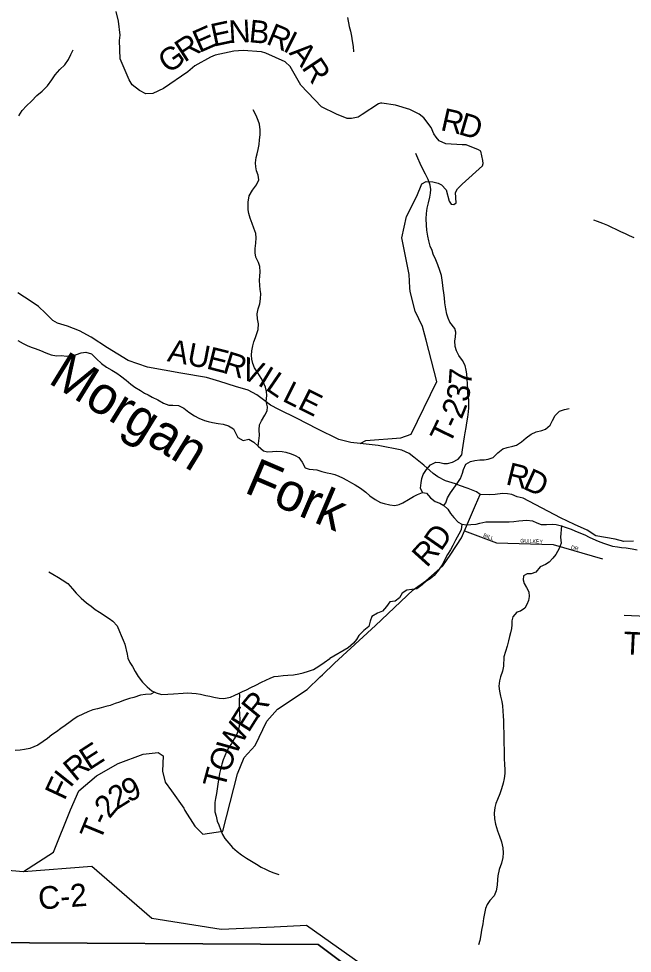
# Model space of a CAD drawing. Extents: x 1578669 to 1989827, y 208020 to 553079.
# Drawn here: x 1759764 to 1767882, y 406595 to 418953 of the extents above; entities that cross this region are included whole.
import ezdxf

# ---------------------------------------------------------------- set-up
doc = ezdxf.new("R2010")
doc.units = 0
for name, color, linetype in [('GM_X_County_Road', 7, 'Continuous'), ('GM_X_County_Road_Text', 7, 'Continuous'), ('GM_X_Minor_River', 7, 'Continuous'), ('GM_X_Minor_River_Text', 7, 'Continuous'), ('GM_X_Township', 7, 'Continuous'), ('GM_X_Township_Road', 7, 'Continuous'), ('GM_X_Township_Road_Text', 7, 'Continuous'), ('GM_X_Township_Subdivision', 7, 'Continuous'), ('GM_X_Township_Subdivision_Text', 7, 'Continuous')]:
    doc.layers.add(name, color=color, linetype=linetype)

msp = doc.modelspace()

# ---------------------------------------------------------------- linework, layer by layer
at = {"layer": 'GM_X_County_Road'}
for points in [[(1767900, 412043), (1767770, 412040), (1767655, 412072), (1767398, 412113), (1767286, 412188), (1767117, 412263), (1766932, 412354), (1766439, 412614), (1766357, 412631), (1766289, 412661), (1766229, 412670), (1766166, 412674), (1766069, 412663), (1765993, 412659), (1765870, 412663), (1765820, 412695), (1765709, 412742), (1765596, 412780), (1765541, 412802), (1765409, 412841), (1765308, 412893), (1765248, 412940), (1765124, 413048), (1764991, 413157), (1764930, 413203), (1764833, 413246), (1764520, 413310), (1764284, 413336), (1764160, 413350), (1764001, 413388), (1763713, 413529), (1763449, 413666), (1763205, 413787), (1763095, 413841), (1763020, 413898), (1762913, 413981), (1762798, 414043), (1762633, 414091), (1762424, 414157), (1762249, 414207), (1761908, 414267), (1761467, 414344), (1761213, 414435), (1760939, 414601), (1760725, 414741), (1760568, 414825), (1760411, 414885), (1760276, 414927), (1760218, 414960), (1760119, 415059), (1760027, 415148), (1759929, 415215), (1759751, 415328)], [(1758349, 408284), (1758363, 408267), (1758628, 407870), (1758709, 407803), (1758726, 407779), (1758795, 407679), (1758805, 407674), (1758871, 407657), (1758962, 407655), (1759126, 407681), (1759270, 407715), (1759375, 407728), (1759549, 407716), (1759674, 407691), (1759826, 407677), (1760733, 407747), (1761526, 407058), (1762445, 406912), (1763145, 406947), (1763146, 406947)], [(1763146, 406947), (1763573, 406968), (1765203, 405810), (1765879, 405766), (1766567, 405904), (1768602, 405235)]]:
    msp.add_lwpolyline(points, dxfattribs=at)
at = {"layer": 'GM_X_Minor_River'}
for points in [[(1764114, 418969), (1764138, 418848), (1764152, 418786), (1764166, 418720), (1764176, 418658), (1764188, 418585), (1764194, 418515)], [(1759764, 417667), (1759812, 417739), (1759868, 417801), (1759932, 417863), (1760006, 417935), (1760075, 417996), (1760145, 418066), (1760203, 418144), (1760247, 418212), (1760309, 418281), (1760373, 418343), (1760425, 418413), (1760453, 418477), (1760483, 418540)], [(1762932, 413302), (1762948, 413442), (1762946, 413515), (1762948, 413581), (1762976, 413635), (1763020, 413709), (1763052, 413768), (1763056, 413820), (1763038, 413892), (1763046, 413972), (1763044, 414024), (1763028, 414081), (1763000, 414151), (1762972, 414201), (1762928, 414271), (1762884, 414338), (1762862, 414392), (1762848, 414452), (1762844, 414504), (1762850, 414563), (1762862, 414625), (1762874, 414679), (1762898, 414737), (1762916, 414789), (1762933, 414844), (1762937, 414920), (1762923, 414986), (1762919, 415052), (1762931, 415115), (1762955, 415183), (1762965, 415249), (1762967, 415319), (1762959, 415372), (1762953, 415424), (1762949, 415494), (1762953, 415550), (1762957, 415604), (1762955, 415677), (1762935, 415731), (1762901, 415801), (1762891, 415855), (1762893, 415914), (1762901, 415984), (1762905, 416054), (1762901, 416112), (1762877, 416185), (1762853, 416243), (1762827, 416313), (1762807, 416375), (1762801, 416425), (1762799, 416476), (1762799, 416528), (1762815, 416612), (1762859, 416686), (1762910, 416757), (1762940, 416821), (1762934, 416885), (1762912, 416941), (1762902, 416996), (1762898, 417046), (1762906, 417116), (1762918, 417166), (1762932, 417224), (1762944, 417287), (1762952, 417349), (1762958, 417417), (1762960, 417483), (1762948, 417558), (1762932, 417608), (1762904, 417674), (1762866, 417746)], [(1765108, 412687), (1765080, 412743), (1765090, 412814), (1765098, 412872), (1765116, 412926), (1765158, 412992), (1765213, 413053), (1765285, 413091), (1765337, 413085), (1765387, 413073), (1765437, 413071), (1765505, 413091), (1765579, 413127), (1765627, 413185), (1765637, 413253), (1765643, 413309), (1765653, 413368), (1765661, 413422), (1765671, 413478), (1765683, 413548), (1765691, 413611), (1765704, 413683), (1765714, 413753), (1765718, 413807), (1765720, 413859), (1765718, 413916), (1765708, 413992), (1765704, 414054), (1765702, 414122), (1765698, 414191), (1765692, 414255), (1765684, 414305), (1765670, 414369), (1765634, 414434), (1765588, 414500), (1765558, 414560), (1765540, 414620), (1765536, 414693), (1765544, 414743), (1765548, 414807), (1765534, 414857), (1765470, 414938), (1765446, 414992), (1765428, 415046), (1765414, 415116), (1765404, 415194), (1765396, 415263), (1765390, 415327), (1765382, 415383), (1765372, 415464), (1765356, 415558), (1765336, 415624), (1765310, 415700), (1765284, 415763), (1765248, 415839), (1765234, 415889), (1765210, 415947), (1765190, 416016), (1765178, 416078), (1765164, 416158), (1765158, 416224), (1765156, 416305), (1765160, 416375), (1765170, 416447), (1765186, 416519), (1765204, 416594), (1765214, 416646), (1765215, 416696), (1765209, 416750), (1765181, 416825), (1765147, 416897), (1765111, 416965), (1765077, 417037), (1765045, 417108), (1765017, 417172)], [(1767906, 416053), (1767844, 416083), (1767794, 416106), (1767731, 416136), (1767667, 416166), (1767611, 416192), (1767557, 416218), (1767493, 416246), (1767423, 416272), (1767371, 416288)], [(1759752, 414697), (1759824, 414659), (1759878, 414633), (1759930, 414611), (1759981, 414591), (1760053, 414565), (1760123, 414535), (1760195, 414509), (1760265, 414497), (1760337, 414499), (1760391, 414491), (1760461, 414495), (1760529, 414511), (1760589, 414533), (1760653, 414545)], [(1760653, 414545), (1760727, 414521), (1760794, 414454), (1760862, 414392), (1760928, 414346), (1760996, 414306), (1761062, 414266), (1761112, 414230), (1761184, 414175), (1761250, 414121), (1761302, 414079), (1761374, 414037), (1761428, 414003), (1761478, 413977), (1761528, 413948), (1761606, 413912), (1761680, 413870), (1761752, 413842), (1761805, 413844), (1761877, 413836), (1761947, 413804), (1762015, 413752), (1762091, 413701), (1762149, 413671), (1762221, 413641), (1762273, 413625), (1762329, 413613), (1762405, 413601), (1762471, 413591), (1762541, 413571), (1762607, 413531), (1762639, 413466), (1762663, 413414), (1762735, 413376), (1762808, 413394), (1762876, 413352), (1762932, 413302), (1763004, 413240), (1763056, 413224), (1763120, 413232), (1763176, 413236), (1763250, 413229), (1763300, 413219), (1763368, 413197), (1763420, 413179), (1763470, 413151), (1763514, 413087), (1763552, 413015), (1763606, 412995), (1763658, 412991), (1763709, 412987), (1763773, 412966), (1763845, 412948), (1763895, 412938), (1763945, 412924), (1763999, 412904), (1764049, 412882), (1764105, 412852), (1764165, 412816), (1764215, 412788), (1764285, 412744), (1764357, 412691), (1764411, 412645), (1764479, 412593), (1764551, 412557), (1764601, 412541), (1764676, 412523), (1764742, 412517), (1764796, 412529), (1764848, 412551), (1764920, 412593), (1764988, 412637), (1765042, 412661), (1765108, 412687), (1765160, 412681), (1765212, 412619), (1765276, 412567), (1765336, 412547), (1765390, 412515), (1765441, 412466), (1765477, 412412), (1765519, 412356), (1765577, 412296), (1765627, 412268), (1765695, 412260), (1765745, 412264), (1765815, 412270), (1765867, 412282), (1765943, 412298), (1766003, 412302), (1766141, 412302), (1766195, 412300), (1766252, 412300), (1766316, 412304), (1766382, 412312), (1766432, 412316), (1766488, 412320), (1766562, 412314), (1766618, 412288), (1766678, 412263), (1766746, 412265)], [(1765390, 412515), (1765415, 412553), (1765435, 412617), (1765477, 412683), (1765523, 412745), (1765573, 412818), (1765611, 412874), (1765637, 412944), (1765647, 412994), (1765681, 413063), (1765743, 413097), (1765797, 413109), (1765867, 413119), (1765924, 413121), (1765976, 413127), (1766042, 413151), (1766104, 413213), (1766170, 413263), (1766226, 413281), (1766302, 413301), (1766352, 413315), (1766418, 413356), (1766476, 413410), (1766542, 413460), (1766611, 413488), (1766683, 413508), (1766735, 413524), (1766795, 413576), (1766827, 413641), (1766861, 413707), (1766921, 413763), (1766985, 413787), (1767045, 413799)], [(1765627, 412268), (1765619, 412195), (1765585, 412135), (1765544, 412059), (1765508, 411989), (1765478, 411928), (1765438, 411868), (1765400, 411800), (1765374, 411746), (1765320, 411661), (1765260, 411591), (1765210, 411547), (1765152, 411511), (1765102, 411469), (1765031, 411412), (1764967, 411404), (1764897, 411398), (1764839, 411358), (1764803, 411294), (1764743, 411250), (1764675, 411244), (1764629, 411180), (1764579, 411117), (1764511, 411091), (1764436, 411047), (1764416, 410987), (1764396, 410917), (1764330, 410861), (1764266, 410798), (1764232, 410746), (1764194, 410696), (1764122, 410636), (1763880, 410493)], [(1766746, 412265), (1766822, 412271), (1766874, 412263), (1766944, 412247), (1766994, 412229), (1767073, 412201), (1767123, 412183), (1767175, 412157), (1767253, 412127), (1767311, 412099), (1767361, 412077), (1767431, 412045), (1767503, 412016), (1767553, 411998), (1767621, 411980), (1767687, 411968), (1767741, 411960), (1767801, 411954), (1767881, 411942), (1767947, 411928)], [(1766944, 412247), (1766934, 412095), (1766942, 412018), (1766916, 411948), (1766870, 411868), (1766832, 411818), (1766784, 411768), (1766734, 411735), (1766662, 411705), (1766606, 411635), (1766542, 411613), (1766491, 411611), (1766441, 411585), (1766439, 411535), (1766453, 411485), (1766483, 411430), (1766511, 411376), (1766519, 411312), (1766507, 411260), (1766487, 411208), (1766461, 411157), (1766405, 411117), (1766355, 411107), (1766301, 411045), (1766289, 410993), (1766287, 410939), (1766283, 410888), (1766269, 410834), (1766259, 410784), (1766245, 410728), (1766227, 410658), (1766181, 410516)], [(1760165, 411640), (1760215, 411608), (1760289, 411564), (1760341, 411534), (1760415, 411483), (1760477, 411413), (1760526, 411357), (1760592, 411289), (1760662, 411230), (1760722, 411184), (1760778, 411142), (1760834, 411106), (1760960, 411022), (1761010, 410987), (1761066, 410925), (1761096, 410849), (1761118, 410795), (1761146, 410735), (1761170, 410684), (1761201, 410548)], [(1761201, 410548), (1761208, 410496), (1761236, 410440), (1761268, 410385), (1761304, 410321), (1761346, 410255), (1761401, 410182), (1761463, 410118), (1761525, 410066), (1761581, 410038), (1761655, 410019), (1761736, 410023), (1761812, 410027), (1761942, 410036), (1761996, 410038), (1762056, 410034), (1762110, 410030), (1762170, 410020), (1762238, 410005), (1762292, 409995), (1762346, 409981), (1762418, 409967), (1762480, 409966), (1762566, 409982), (1762622, 410006), (1762674, 410032), (1762724, 410056), (1762778, 410080), (1762836, 410108), (1762900, 410139), (1762976, 410181), (1763032, 410207), (1763090, 410231), (1763146, 410253), (1763198, 410261), (1763262, 410269), (1763326, 410272), (1763400, 410278), (1763470, 410290), (1763526, 410302), (1763600, 410326), (1763666, 410349), (1763736, 410391), (1763806, 410439), (1763880, 410493)], [(1766181, 410516), (1766180, 410393), (1766166, 410325), (1766140, 410249), (1766126, 410197), (1766115, 410127), (1766125, 410059), (1766139, 409997), (1766157, 409924), (1766165, 409866), (1766170, 409798), (1766174, 409736), (1766176, 409670), (1766178, 409592), (1766181, 409505), (1766183, 409413), (1766183, 409363), (1766185, 409295), (1766188, 409243), (1766188, 409169), (1766192, 409090), (1766196, 409024), (1766195, 408972), (1766185, 408904), (1766173, 408846), (1766153, 408768), (1766131, 408704), (1766098, 408630), (1766076, 408576), (1766062, 408524), (1766054, 408450), (1766060, 408371), (1766073, 408301), (1766099, 408213), (1766125, 408143), (1766150, 408070), (1766170, 407988), (1766174, 407924), (1766168, 407860), (1766150, 407788), (1766121, 407702), (1766101, 407620), (1766097, 407569), (1766095, 407495), (1766082, 407421), (1766054, 407353), (1765996, 407295), (1765962, 407241), (1765942, 407187), (1765925, 407119), (1765913, 407055), (1765903, 406983), (1765889, 406901), (1765879, 406841), (1765864, 406762), (1765848, 406708)], [(1761561, 410048), (1761513, 410022), (1761443, 410018), (1761375, 410006), (1761287, 409978), (1761231, 409963), (1761153, 409939), (1761099, 409917), (1761039, 409897), (1760973, 409873), (1760917, 409857), (1760857, 409839), (1760805, 409828), (1760745, 409814), (1760678, 409788), (1760612, 409756), (1760548, 409726), (1760498, 409694), (1760446, 409656), (1760378, 409609), (1760322, 409569), (1760264, 409525), (1760204, 409483), (1760146, 409437), (1760088, 409397), (1760016, 409349), (1759965, 409325), (1759911, 409301), (1759839, 409290), (1759785, 409280), (1759716, 409276)], [(1762683, 410036), (1762686, 410010), (1762681, 409936), (1762681, 409882), (1762683, 409825), (1762687, 409761), (1762689, 409683), (1762682, 409599), (1762666, 409539), (1762644, 409485), (1762616, 409429), (1762578, 409367), (1762545, 409315), (1762515, 409259), (1762491, 409205), (1762471, 409151), (1762451, 409095), (1762437, 409043), (1762422, 408972), (1762412, 408914), (1762400, 408832), (1762390, 408770), (1762380, 408706), (1762369, 408640), (1762361, 408590), (1762357, 408514), (1762361, 408464), (1762375, 408407), (1762392, 408343), (1762410, 408293), (1762436, 408233), (1762460, 408165), (1762491, 408114), (1762543, 408050), (1762595, 407996), (1762655, 407943), (1762713, 407899), (1762776, 407855), (1762912, 407774), (1762974, 407732), (1763028, 407708), (1763084, 407682), (1763139, 407661), (1763207, 407637)]]:
    msp.add_lwpolyline(points, dxfattribs=at)
at = {"layer": 'GM_X_Township'}
for points in [[(1765263, 405555), (1763728, 406710), (1759141, 406736)], [(1759141, 406736), (1763728, 406710), (1765263, 405555)]]:
    msp.add_lwpolyline(points, dxfattribs=at)
at = {"layer": 'GM_X_Township_Road'}
for points in [[(1764941, 415395), (1764934, 415484), (1764928, 415569), (1764834, 416053), (1764893, 416336), (1765033, 416607), (1765098, 416771), (1765157, 416798), (1765243, 416795), (1765315, 416777), (1765357, 416758), (1765418, 416690), (1765459, 416539), (1765485, 416498), (1765521, 416494), (1765553, 416518), (1765541, 416656), (1765569, 416705), (1765632, 416765), (1765899, 417008), (1765909, 417039), (1765906, 417077), (1765876, 417200), (1765848, 417217), (1765684, 417283), (1765632, 417284), (1765417, 417299), (1765329, 417339), (1765287, 417384), (1765258, 417429), (1765219, 417512), (1765125, 417640), (1765061, 417692), (1764941, 417751), (1764749, 417810), (1764569, 417835), (1764549, 417837), (1764525, 417828), (1764307, 417684), (1764254, 417650), (1764169, 417634), (1764110, 417634), (1763970, 417689), (1763770, 417789), (1763499, 418072), (1763355, 418322), (1763288, 418381), (1763033, 418496), (1762976, 418515), (1762735, 418530), (1762611, 418521), (1762365, 418469), (1762302, 418443), (1762093, 418328), (1762004, 418251), (1761681, 418031), (1761540, 417963), (1761448, 417960), (1761363, 418003), (1761266, 418078), (1761228, 418144), (1761106, 418421), (1761097, 418663), (1761105, 418734), (1761084, 418919), (1761053, 419049)], [(1765154, 414702), (1765137, 414766), (1765107, 414881), (1765011, 415087), (1764944, 415345), (1764941, 415395)], [(1764284, 413336), (1764358, 413377), (1764820, 413412), (1764955, 413461), (1765297, 414154), (1765154, 414702)], [(1763784, 410278), (1763944, 410433), (1764485, 410930), (1764983, 411401), (1765152, 411521), (1765374, 411720), (1765481, 411874), (1765623, 412089), (1765660, 412179), (1765808, 412520), (1765870, 412663)], [(1767776, 411068), (1768564, 411031), (1768614, 411031)], [(1761964, 408485), (1762094, 408277), (1762201, 408168), (1762467, 408211), (1762661, 408966), (1762749, 409183), (1762891, 409341), (1763045, 409666), (1763188, 409823), (1763582, 410082), (1763753, 410249), (1763784, 410278)], [(1759826, 407677), (1760227, 407934), (1760449, 408493), (1760558, 408743), (1760794, 408940), (1761081, 409106), (1761410, 409227), (1761609, 409249), (1761674, 409205), (1761665, 409003), (1761701, 408858), (1761787, 408745), (1761947, 408512), (1761953, 408503), (1761964, 408485)]]:
    msp.add_lwpolyline(points, dxfattribs=at)
at = {"layer": 'GM_X_Township_Subdivision'}
msp.add_lwpolyline([(1765660, 412179), (1766084, 412024), (1766833, 411998), (1767487, 411811)], dxfattribs=at)

# ---------------------------------------------------------------- texts
at = {"layer": 'GM_X_County_Road_Text'}
for s, rotation, p in [('A', 349.5753, (1761721, 414425)), ('U', 349.2344, (1761980, 414377)), ('E', 345.732, (1762235, 414329)), ('R', 342.6166, (1762448, 414275)), ('V', 339.3574, (1762679, 414203)), ('I', 328.6681, (1762913, 414116)), ('L', 325.4981, (1763015, 414055)), ('L', 333.2666, (1763238, 413905)), ('E', 333.5942, (1763440, 413803)), ('R', 346.1379, (1766195, 412798)), ('D', 335.4424, (1766421, 412744)), ('C-2', 4.5732, (1760034, 407172))]:
    msp.add_text(s, height=300, rotation=rotation, dxfattribs=at).set_placement(p)
at = {"layer": 'GM_X_Minor_River_Text'}
for s, rotation, p in [('Morgan', 328.3215, (1760140, 414145)), ('Fork', 336.8506, (1762733, 412694))]:
    msp.add_text(s, height=500, rotation=rotation, dxfattribs=at).set_placement(p)
at = {"layer": 'GM_X_Township_Road_Text'}
for s, rotation, p in [('N', 3.2657, (1762550, 418628)), ('B', 354.3275, (1762801, 418643)), ('E', 23.7754, (1762153, 418496)), ('E', 12.1899, (1762343, 418582)), ('R', 337.3093, (1763024, 418624)), ('R', 32.9897, (1761957, 418368)), ('I', 333.2813, (1763246, 418532)), ('G', 35.2916, (1761744, 418218)), ('A', 311.4327, (1763332, 418495)), ('R', 303.7929, (1763500, 418305)), ('R', 347.2731, (1765333, 417482)), ('D', 343.7174, (1765569, 417429)), ('7', 85.9732, (1765750, 414096)), ('3', 78.8349, (1765709, 413874)), ('2', 68.4441, (1765624, 413646)), ('T', 63.8643, (1765463, 413309)), ('-', 64.877, (1765564, 413515)), ('D', 55.2855, (1765352, 411900)), ('R', 48.0041, (1765162, 411685)), ('T', 357.2647, (1767760, 410550)), ('R', 50.6837, (1762919, 409682)), ('E', 57.7043, (1762805, 409501)), ('W', 59.6113, (1762630, 409203)), ('E', 32.7831, (1760694, 409008)), ('O', 69.4704, (1762543, 408968)), ('R', 39.5912, (1760512, 408857)), ('T', 74.917, (1762487, 408759)), ('F', 65.0374, (1760371, 408605)), ('I', 51.4438, (1760446, 408772)), ('9', 25.4152, (1761214, 408584)), ('2', 32.1196, (1761066, 408490)), ('2', 49.9592, (1760965, 408365)), ('-', 65.3868, (1760925, 408271)), ('T', 67.6916, (1760842, 408066))]:
    msp.add_text(s, height=300, rotation=rotation, dxfattribs=at).set_placement(p)
at = {"layer": 'GM_X_Township_Subdivision_Text'}
for s, rotation, p in [('BILL', 339.2246, (1765905, 412104)), ('GUILKEY', 357.6153, (1766399, 412026)), ('DR', 345.2513, (1767066, 411942))]:
    msp.add_text(s, height=50, rotation=rotation, dxfattribs=at).set_placement(p)

doc.saveas('drawing.dxf')
